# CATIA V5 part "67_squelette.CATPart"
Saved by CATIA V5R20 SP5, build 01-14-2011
Part number: 67_squelette
Publications: "Plan.1", "Point.1", "Point.3", "Plan.3", "Point.6", "Point.5"
Bounding box of the stored display mesh (mm): x 0 to 0, y 140.362 to 160.862, z 170 to 170
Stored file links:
  C:\Documents and Settings\anizard\Bureau\13\67_squelette.CATPart
  C:\Documents and Settings\anizard\Bureau\13\anizard.CATProduct
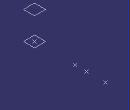
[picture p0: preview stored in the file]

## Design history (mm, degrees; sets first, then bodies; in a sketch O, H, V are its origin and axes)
Set1
  Plane1: linked copy from another document
  Point1: linked copy from another document
  Point2: linked copy from another document
Body1 (main body)
  Plane2: type Offset, RefPlane Plane1, Offset 23.5
  Point3: type OnPlane, Support Plane2, RefPoint Point2, H 0, V 0, Direction (1, 0, 0)
  Point4: (0, 15, 0), relative to Point3
  Plane3: type Offset, RefPlane Plane2, Offset 8
  Point5: (0, 11.75, 0), relative to Point3
  Point6: (0, 20.5, 0), relative to Point3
